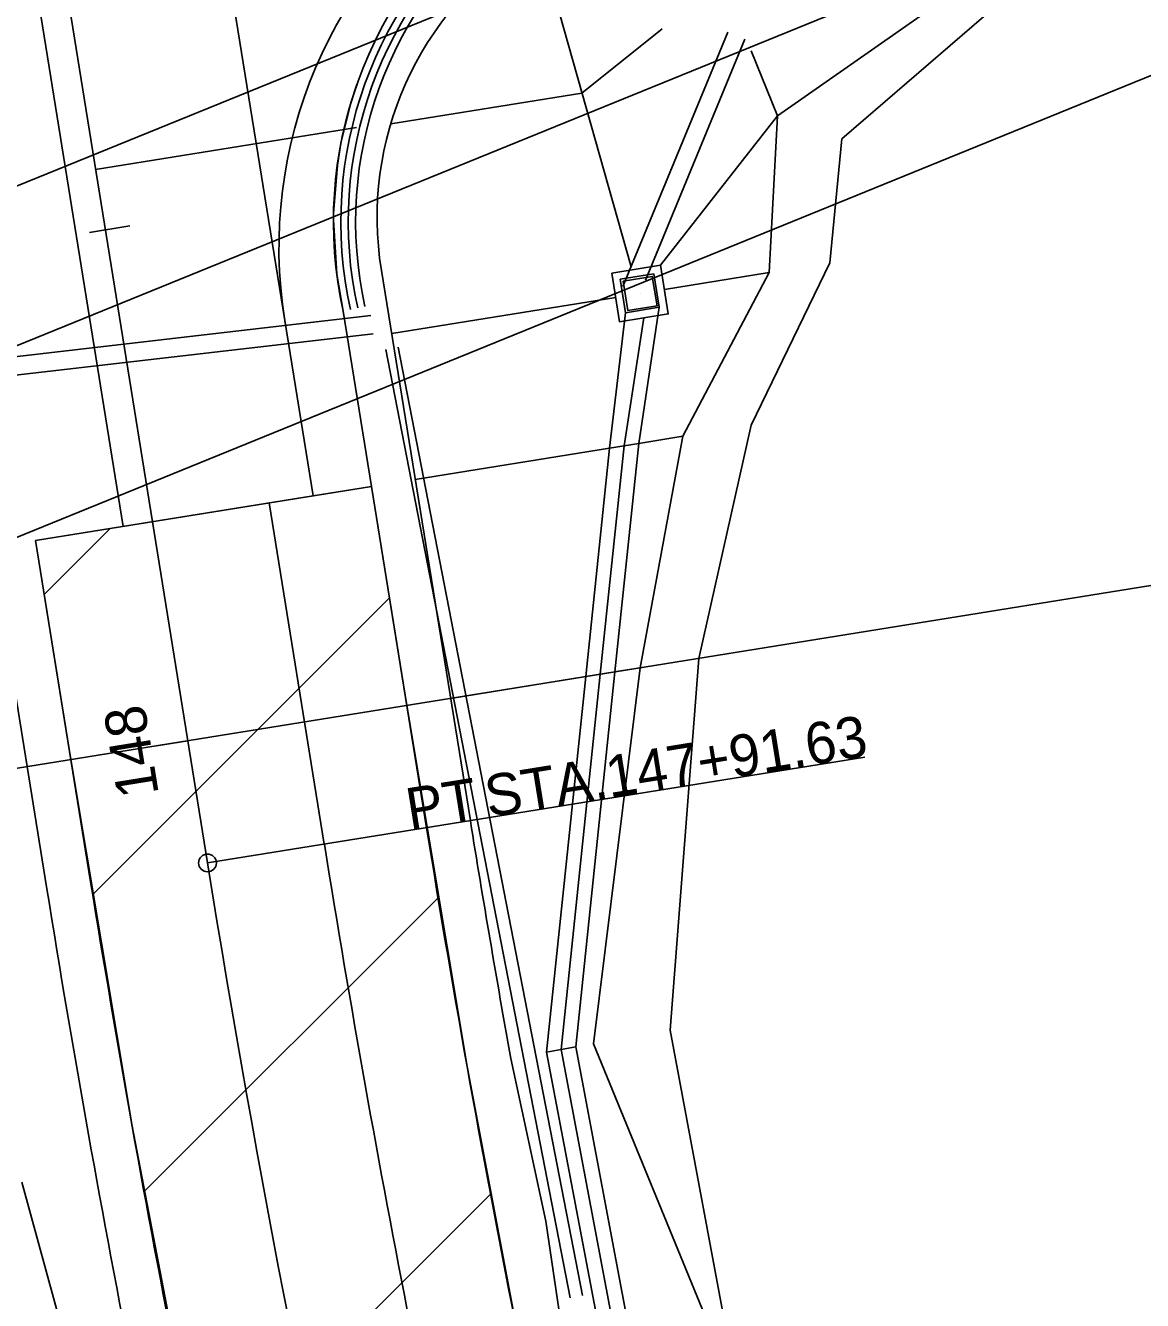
# Model space of a CAD drawing. Extents: x 195197 to 195502, y 336876 to 337459.
# Drawn here: x 195324.5 to 195400.1, y 337094.6 to 337180.8 of the extents above; entities that cross this region are included whole.
import ezdxf

# ---------------------------------------------------------------- set-up
doc = ezdxf.new("R2010")
doc.units = 0
for name, color, linetype in [('_CIVIL_CONSTRUCTION', 7, 'Continuous'), ('DR_P_Cells', 7, 'Continuous'), ('DR_P_Headwall', 7, 'Continuous'), ('DT_X_Contour_Major', 7, 'Continuous'), ('DT_X_Contour_Minor', 7, 'Continuous'), ('DT_X_Contour_Text', 7, 'Continuous'), ('DT_X_Island', 7, 'Continuous'), ('DT_X_Terrain_Boundary', 7, 'Continuous'), ('DT_X_Triangles', 7, 'Continuous'), ('DT_X_Void', 7, 'Continuous'), ('GK_Drainage_Nodes', 7, 'Continuous'), ('PV_P_Shoulder', 7, 'Continuous'), ('SC_Scratch1', 7, 'Continuous'), ('SH_Major_Grid_Line', 7, 'Continuous')]:
    doc.layers.add(name, color=color, linetype=linetype)

msp = doc.modelspace()

# ---------------------------------------------------------------- linework, layer by layer
at = {"layer": '_CIVIL_CONSTRUCTION'}
for points in [[(195378.921, 337164.757), (195379.72, 337173.142), (195391.448, 337183.271), (195402.662, 337190.803), (195415.156, 337192.634)], [(195384.304, 336949.34), (195397.966, 336955.533), (195391.338, 336968.426), (195383.812, 336991.345), (195376.657, 337014.554), (195375.006, 337039.552), (195376.79, 337065.025), (195372.56, 337089.055), (195368.123, 337112.863), (195370.066, 337138.006), (195373.602, 337153.77), (195378.921, 337164.757)]]:
    msp.add_lwpolyline(points, dxfattribs=at)
at = {"layer": 'DR_P_Cells'}
for p, q in [((195300.457, 337280.746), (195325.985, 337122.421)), ((195342.072, 337160.853), (195343.984, 337148.995)), ((195325.226, 337145.97), (195343.984, 337148.995)), ((195325.226, 337145.97), (195328.946, 337122.898))]:
    msp.add_line(p, q, dxfattribs=at)
for centre, radius, start, end in [((195372.675, 337165.798), 31, 124.66642, 189.17838), ((196294.35, 337278.214), 977.817, 189.139559, 193.075816), ((196294.35, 337278.214), 980.817, 189.13959, 193.075816)]:
    msp.add_arc(centre, radius, start, end, dxfattribs=at)
at = {"layer": 'DR_P_Headwall'}
for p, q in [((195335.512, 337132.435), (195333.538, 337132.117)), ((195336.845, 337124.17), (195381.271, 337131.333))]:
    msp.add_line(p, q, dxfattribs=at)
msp.add_circle((195336.845, 337124.17), 0.6, dxfattribs=at)
at = {"layer": 'DT_X_Contour_Major'}
msp.add_lwpolyline([(195364.323, 337092.659), (195360.751, 337111.547), (195363.399, 337136.931), (195365.011, 337152.385), (195366.352, 337161.042)], dxfattribs=at)
at = {"layer": 'DT_X_Contour_Minor'}
for points in [[(195364.176, 337164.068), (195367.466, 337164.598), (195367.997, 337161.307), (195364.706, 337160.777)], [(195364.746, 337163.648), (195367.009, 337164.012), (195367.373, 337161.75), (195365.111, 337161.385)], [(195364.94, 337163.516), (195366.914, 337163.834), (195367.233, 337161.86), (195365.258, 337161.541)]]:
    msp.add_lwpolyline(points, close=True, dxfattribs=at)
at = {"layer": 'DT_X_Contour_Text'}
for p, q in [((195365.821, 337164.333), (195365.821, 337164.333)), ((195365.927, 337163.675), (195365.927, 337163.675)), ((195365.099, 337162.528), (195365.099, 337162.528)), ((195366.086, 337162.688), (195366.086, 337162.688)), ((195366.086, 337162.688), (195366.086, 337162.688)), ((195366.086, 337162.688), (195366.086, 337162.688)), ((195367.074, 337162.847), (195367.074, 337162.847)), ((195366.246, 337161.7), (195366.246, 337161.7)), ((195366.352, 337161.042), (195366.352, 337161.042))]:
    msp.add_line(p, q, dxfattribs=at)
at = {"layer": 'DT_X_Island'}
for points in [[(195347.933, 337149.631), (195351.654, 337126.555), (195351.654, 337126.553)], [(195341.022, 337148.517), (195344.743, 337125.442), (195344.743, 337125.441)]]:
    msp.add_lwpolyline(points, dxfattribs=at)
for radius, end in [(954.817, 191.236963), (961.817, 193.075816)]:
    msp.add_arc((196294.35, 337278.214), radius, 189.139478, end, dxfattribs=at)
at = {"layer": 'DT_X_Terrain_Boundary'}
for p, q in [((195348.908, 337158.903), (195361.373, 337094.767)), ((195349.726, 337159.062), (195362.191, 337094.926))]:
    msp.add_line(p, q, dxfattribs=at)
for points in [[(195347.892, 337161.198), (195308.05, 337156.581), (195299.686, 337154.73)], [(195348.036, 337159.956), (195308.257, 337155.347), (195299.956, 337153.51)]]:
    msp.add_lwpolyline(points, dxfattribs=at)
at = {"layer": 'DT_X_Triangles'}
for p, q in [((195364.927, 337163.166), (195372.014, 337180.352)), ((195366.455, 337163.592), (195373.17, 337179.875))]:
    msp.add_line(p, q, dxfattribs=at)
at = {"layer": 'DT_X_Void'}
for p, q in [((195325.814, 337142.325), (195330.273, 337146.784)), ((195329.131, 337122.072), (195349.149, 337142.09)), ((195332.596, 337101.966), (195352.484, 337121.855)), ((195336.39, 337082.19), (195356.014, 337101.815))]:
    msp.add_line(p, q, dxfattribs=at)
msp.add_lwpolyline([(195352.312, 337008.933), (195346.318, 337032.105), (195340.667, 337056.71), (195341.886, 337056.993), (195336.5, 337081.616), (195331.751, 337106.37), (195327.614, 337131.162), (195325.226, 337145.97), (195347.933, 337149.631), (195350.321, 337134.823), (195354.393, 337110.412), (195357.837, 337092.152), (195358.722, 337086.177), (195362.341, 337061.744), (195360.671, 337061.356), (195360.874, 337060.453), (195365.755, 337039.781), (195370.377, 337021.873)], dxfattribs=at)
at = {"layer": 'GK_Drainage_Nodes'}
for p, q in [((195346.021, 337161.49), (195347.933, 337149.631)), ((195347.933, 337149.631), (195343.984, 337148.995)), ((195337.015, 337055.862), (195324.302, 337102.591))]:
    msp.add_line(p, q, dxfattribs=at)
msp.add_arc((195373.36, 337167.539), 28, 127.8475, 192.4752, dxfattribs=at)
at = {"layer": 'PV_P_Shoulder'}
for p, q in [((195375.389, 337174.701), (195396.8, 337189.711)), ((195359.155, 337186.893), (195365.476, 337164.496)), ((195367.59, 337180.594), (195362.161, 337176.242)), ((195373.597, 337179.1), (195375.389, 337174.701)), ((195349.231, 337174.157), (195362.161, 337176.242)), ((195375.389, 337174.701), (195367.466, 337164.598)), ((195374.811, 337164.094), (195375.389, 337174.701)), ((195374.811, 337164.094), (195367.732, 337162.953)), ((195368.98, 337153.025), (195374.811, 337164.094)), ((195349.303, 337159.982), (195364.441, 337162.422)), ((195364.024, 337152.226), (195365.111, 337161.385)), ((195365.999, 337152.544), (195367.373, 337161.75)), ((195368.98, 337153.025), (195365.999, 337152.544)), ((195368.98, 337153.025), (195366.094, 337137.366)), ((195350.895, 337150.109), (195364.024, 337152.226)), ((195362.412, 337136.772), (195364.024, 337152.226)), ((195364.386, 337137.091), (195365.999, 337152.544)), ((195362.95, 337111.94), (195366.094, 337137.366)), ((195366.094, 337137.366), (195364.491, 337137.108)), ((195353.283, 337135.3), (195362.412, 337136.772)), ((195359.766, 337111.372), (195362.412, 337136.772)), ((195361.735, 337111.723), (195364.386, 337137.091)), ((195359.766, 337111.372), (195363.334, 337092.513)), ((195361.735, 337111.723), (195365.312, 337092.806)), ((195362.95, 337111.94), (195370.856, 337092.631)), ((195357.346, 337110.94), (195359.707, 337099.934)), ((195359.707, 337099.934), (195365.263, 337062.423))]:
    msp.add_line(p, q, dxfattribs=at)
msp.add_lwpolyline([(195354.616, 337127.029), (195354.616, 337127.032), (195348.481, 337165.078)], dxfattribs=at)
for centre, radius, start, end in [((195370.484, 337167.831), 22.174, 120.72461, 187.13207), ((196294.35, 337278.214), 951.817, 189.139478, 190.121869)]:
    msp.add_arc(centre, radius, start, end, dxfattribs=at)
at = {"layer": 'SC_Scratch1'}
msp.add_line((195336.845, 337124.17), (195282.881, 337458.86), dxfattribs=at)
msp.add_arc((196294.35, 337278.214), 969.817, 189.139478, 196.615985, dxfattribs=at)
at = {"layer": 'SH_Major_Grid_Line'}
for p, q in [((195395.663, 337199.154), (195292.862, 337157.287)), ((195399.435, 337189.893), (195296.633, 337148.025)), ((195337.617, 337188.485), (195342.072, 337160.853)), ((195331.15, 337146.925), (195324.783, 337186.415)), ((195403.961, 337178.779), (195301.16, 337136.912)), ((195346.541, 337175.585), (195346.941, 337176.816)), ((195345.868, 337172.849), (195346.541, 337175.585)), ((195329.284, 337171.062), (195346.925, 337173.906)), ((195345.623, 337171.367), (195345.868, 337172.849)), ((195345.365, 337168.088), (195345.623, 337171.367)), ((195345.36, 337167.67), (195345.365, 337168.088)), ((195345.586, 337163.985), (195345.36, 337167.67)), ((195331.585, 337167.254), (195328.874, 337166.817)), ((195346.021, 337161.491), (195345.586, 337163.985)), ((195197.297, 337110.15), (195502.355, 337159.336)), ((195364.024, 337152.226), (195365.999, 337152.544)), ((195362.412, 337136.772), (195364.386, 337137.091)), ((195359.766, 337111.372), (195361.735, 337111.723))]:
    msp.add_line(p, q, dxfattribs=at)
for radius in [27.5, 27, 26.5]:
    msp.add_arc((195373.36, 337167.539), radius, 127.8475, 192.4752, dxfattribs=at)

# ---------------------------------------------------------------- texts
at = {"layer": 'DR_P_Headwall'}
for s, rotation, p in [('148', 99.15931, (195333.561, 337128.829)), ('147+91.63', 9.15931, (195364.019, 337128.589)), (' STA. ', 9.15931, (195354.815, 337127.105)), ('PT', 9.15931, (195350.519, 337126.412))]:
    msp.add_text(s, height=2.8, rotation=rotation, dxfattribs=at).set_placement(p)

doc.saveas('drawing.dxf')
